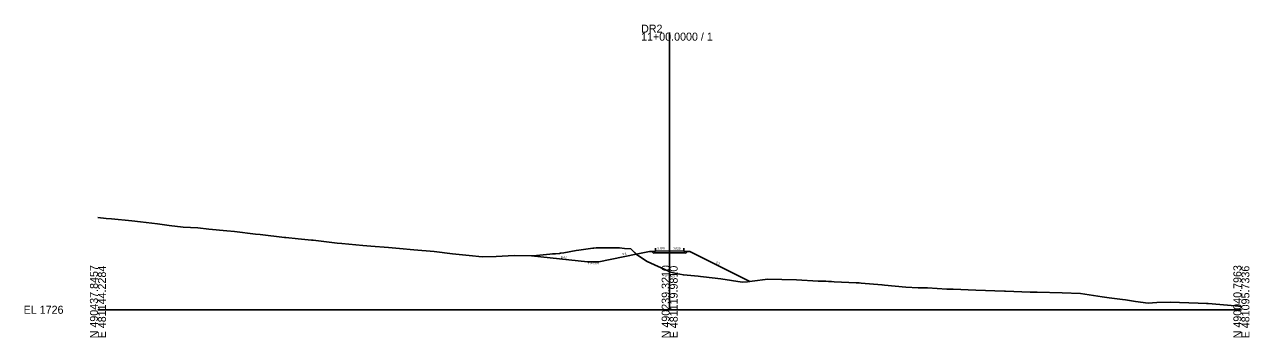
# Model space of a CAD drawing. Extents: x -26 to 403, y -10 to 2576.
# Drawn here: x -25.7 to 402.8, y 990.3 to 1099.7 of the extents above; entities that cross this region are included whole.
import ezdxf

# ---------------------------------------------------------------- set-up
doc = ezdxf.new("R2010")
doc.units = 0
for name, color, linetype in [('Exist Cross Section Cell', 7, 'Continuous'), ('Exist XS Center Line Elevation Label', 7, 'Continuous'), ('Exist XS Ground Line', 7, 'Continuous'), ('Prop Road Sect_ Boring - Header (ID Tx)', 7, 'Continuous'), ('Prop XS Ditch Standard Text', 7, 'Continuous'), ('Prop XS Dump Level', 7, 'Continuous'), ('Prop XS Earthwork Shape', 7, 'Continuous'), ('Prop XS EOT Tick Mark', 7, 'Continuous'), ('Prop XS Finish Grade', 7, 'Continuous'), ('Prop XS Finish Grade Earthwork', 7, 'Continuous'), ('Prop XS Finish Grade Pavement', 7, 'Continuous'), ('Prop XS Pvmt Edge Slope', 7, 'Continuous'), ('Prop XS SE Text', 7, 'Continuous'), ('Prop XS Side Slope Text', 7, 'Continuous'), ('Prop XS Subgrade Earthwork', 7, 'Continuous')]:
    doc.layers.add(name, color=color, linetype=linetype)

msp = doc.modelspace()

# ---------------------------------------------------------------- linework, layer by layer
at = {"layer": 'Exist Cross Section Cell'}
for p, q in [((200, 1000), (200, 1096.86)), ((0, 1000), (200, 1000)), ((200, 1000), (400, 1000))]:
    msp.add_line(p, q, dxfattribs=at)
at = {"layer": 'Exist XS Ground Line'}
msp.add_lwpolyline([(0, 1032.29), (2.88, 1031.95), (4.76, 1031.75), (11.86, 1031.04), (14.84, 1030.68), (20.84, 1030.04), (24.91, 1029.43), (29.82, 1028.9), (34.99, 1028.62), (38.8, 1028.13), (45.07, 1027.61), (47.78, 1027.31), (55.14, 1026.45), (56.76, 1026.27), (65.22, 1025.31), (65.74, 1025.25), (70, 1024.83), (74.72, 1024.37), (75.29, 1024.31), (83.7, 1023.32), (85.37, 1023.12), (92.68, 1022.5), (95.45, 1022.2), (101.66, 1021.81), (105.52, 1021.46), (110.47, 1020.99), (117.61, 1020.37), (123.99, 1019.58), (129.89, 1019), (134.42, 1018.46), (139.27, 1018.58), (145.62, 1018.94), (152.26, 1018.87), (158.05, 1019.38), (159.12, 1019.57), (160.05, 1019.6), (161.5, 1019.7), (161.83, 1019.73), (162.92, 1019.85), (167.32, 1020.7), (168.25, 1020.83), (173.12, 1021.54), (173.42, 1021.58), (174.29, 1021.59), (182.48, 1021.66), (184.21, 1021.46), (186.36, 1021.27), (188.7, 1019.03), (192.11, 1016.9), (199.54, 1013.43), (200, 1013.3), (202.32, 1012.63), (204.82, 1012.15), (210, 1011.69), (210.83, 1011.61), (211.83, 1011.51), (217.91, 1010.83), (225.39, 1009.59), (227.24, 1009.77), (228.86, 1009.96), (234.33, 1010.72), (239.25, 1010.54), (244.37, 1010.46), (251.95, 1009.94), (253.71, 1009.98), (254.62, 1009.97), (255.55, 1009.93), (256.62, 1009.86), (257.51, 1009.77), (265.22, 1009.44), (266.29, 1009.36), (267, 1009.28), (274.27, 1008.73), (275.16, 1008.58), (282.64, 1007.94), (286.9, 1007.72), (290.23, 1007.64), (296.97, 1007.22), (299.21, 1007.19), (307.05, 1006.84), (317.11, 1006.53), (317.5, 1006.51), (326.14, 1006.17), (327.2, 1006.14), (328.55, 1006.11), (337.26, 1005.87), (343.76, 1005.68), (351.32, 1004.53), (353.79, 1004.19), (358.38, 1003.57), (359.43, 1003.43), (363, 1002.92), (367.37, 1002.29), (370.38, 1002.54), (375.05, 1002.65), (384.86, 1002.3), (387.75, 1002.21), (388.36, 1002.13), (397.83, 1001.4), (400, 1001.16)], dxfattribs=at)
at = {"layer": 'Prop Road Sect_ Boring - Header (ID Tx)'}
for points in [[(195, 1020.52), (193.74, 1020.41), (194.32, 1019.83)], [(205, 1020.52), (206.26, 1020.41), (205.68, 1019.83)]]:
    msp.add_lwpolyline(points, close=True, dxfattribs=at)
at = {"layer": 'Prop XS Dump Level'}
for p, q in [((195, 1020.52), (200, 1020.62)), ((200, 1020.62), (205, 1020.52))]:
    msp.add_line(p, q, dxfattribs=at)
at = {"layer": 'Prop XS Earthwork Shape'}
for p, q in [((168.25, 1020.83), (167.32, 1020.7)), ((173.12, 1021.54), (168.25, 1020.83)), ((173.42, 1021.58), (173.12, 1021.54)), ((188.3, 1019.41), (186.36, 1021.27)), ((152.26, 1018.87), (151.68, 1018.88)), ((151.68, 1018.87), (171.22, 1016.8)), ((171.22, 1016.8), (175.22, 1016.8)), ((175.22, 1016.8), (188.3, 1019.41))]:
    msp.add_line(p, q, dxfattribs=at)
for points in [[(167.32, 1020.7), (162.92, 1019.85), (161.83, 1019.73), (161.5, 1019.7), (160.05, 1019.6)], [(186.36, 1021.27), (184.21, 1021.46), (182.48, 1021.66), (174.29, 1021.59), (173.42, 1021.58)], [(151.68, 1018.88), (151.68, 1018.87)], [(160.05, 1019.6), (159.12, 1019.57), (158.05, 1019.38), (152.26, 1018.87)]]:
    msp.add_lwpolyline(points, dxfattribs=at)
msp.add_lwpolyline([(193.74, 1020.41), (193, 1020.36), (188.3, 1019.41), (188.7, 1019.03), (192.11, 1016.9), (199.54, 1013.43), (200, 1013.3), (202.32, 1012.63), (204.82, 1012.15), (210, 1011.69), (210.83, 1011.61), (211.83, 1011.51), (217.91, 1010.83), (225.39, 1009.59), (227.24, 1009.77), (228, 1009.86), (207, 1020.36), (206.26, 1020.41), (205.68, 1019.83), (205, 1019.85), (200, 1019.95), (195, 1019.85), (194.32, 1019.83)], close=True, dxfattribs=at)
at = {"layer": 'Prop XS EOT Tick Mark'}
for p, q in [((195, 1020.52), (195, 1021.52)), ((205, 1020.52), (205, 1021.52))]:
    msp.add_line(p, q, dxfattribs=at)
at = {"layer": 'Prop XS Finish Grade'}
for p, q in [((195, 1020.52), (193.74, 1020.41)), ((205, 1020.52), (206.26, 1020.41))]:
    msp.add_line(p, q, dxfattribs=at)
at = {"layer": 'Prop XS Finish Grade Earthwork'}
for p, q in [((193, 1020.36), (188.3, 1019.41)), ((193.74, 1020.41), (193, 1020.36)), ((206.26, 1020.41), (207, 1020.36)), ((207, 1020.36), (228, 1009.86)), ((151.68, 1018.87), (171.22, 1016.8)), ((171.22, 1016.8), (175.22, 1016.8)), ((175.22, 1016.8), (188.3, 1019.41))]:
    msp.add_line(p, q, dxfattribs=at)
at = {"layer": 'Prop XS Finish Grade Pavement'}
for p, q in [((195, 1020.52), (200, 1020.62)), ((200, 1020.62), (205, 1020.52))]:
    msp.add_line(p, q, dxfattribs=at)
at = {"layer": 'Prop XS Pvmt Edge Slope'}
for p, q in [((195, 1020.52), (194.32, 1019.83)), ((205, 1020.52), (205.68, 1019.83))]:
    msp.add_line(p, q, dxfattribs=at)
at = {"layer": 'Prop XS Subgrade Earthwork'}
for p, q in [((194.32, 1019.83), (193.74, 1020.41)), ((200, 1019.95), (195, 1019.85)), ((205, 1019.85), (200, 1019.95)), ((205.68, 1019.83), (206.26, 1020.41)), ((195, 1019.85), (194.32, 1019.83)), ((205, 1019.85), (205.68, 1019.83))]:
    msp.add_line(p, q, dxfattribs=at)

# ---------------------------------------------------------------- texts
at = {"layer": 'Exist Cross Section Cell'}
for s, p in [('DR2', (190, 1096.86)), ('11+00.0000 / 1', (190, 1094.06)), ('EL 1726', (-26, 998.6))]:
    msp.add_text(s, height=2.8, dxfattribs=at).set_placement(p)
for s, p in [('N 490437.8457', (0, 990)), ('E 481144.2284', (2.8, 990)), ('N 490239.3210', (200, 990)), ('E 481119.9810', (202.8, 990)), ('N 490040.7963', (400, 990)), ('E 481095.7336', (402.8, 990))]:
    msp.add_text(s, height=2.8, rotation=90, dxfattribs=at).set_placement(p)
at = {"layer": 'Exist XS Center Line Elevation Label'}
msp.add_text('1739.30', height=0.75, dxfattribs=at).set_placement((198.14, 1011.3))
at = {"layer": 'Prop XS Ditch Standard Text'}
msp.add_text('1742.80', height=0.75, dxfattribs=at).set_placement((171.38, 1015.83))
at = {"layer": 'Prop XS Dump Level'}
for p in [(193, 1020.32), (207, 1020.32)]:
    msp.add_text('Case1', height=0.04, dxfattribs=at).set_placement(p)
at = {"layer": 'Prop XS SE Text'}
for rotation, p in [(1.1458, (195.71, 1021.04)), (358.8542, (201.18, 1021.09))]:
    msp.add_text('0.020', height=0.75, rotation=rotation, dxfattribs=at).set_placement(p)
at = {"layer": 'Prop XS Side Slope Text'}
for s, rotation, p in [('5:1', 9.0768, (183.57, 1019.08)), ('9.4:1', 354.2403, (161.89, 1018.02)), ('2:1', 333.4349, (216.1, 1016.29))]:
    msp.add_text(s, height=0.75, rotation=rotation, dxfattribs=at).set_placement(p)

doc.saveas('drawing.dxf')
